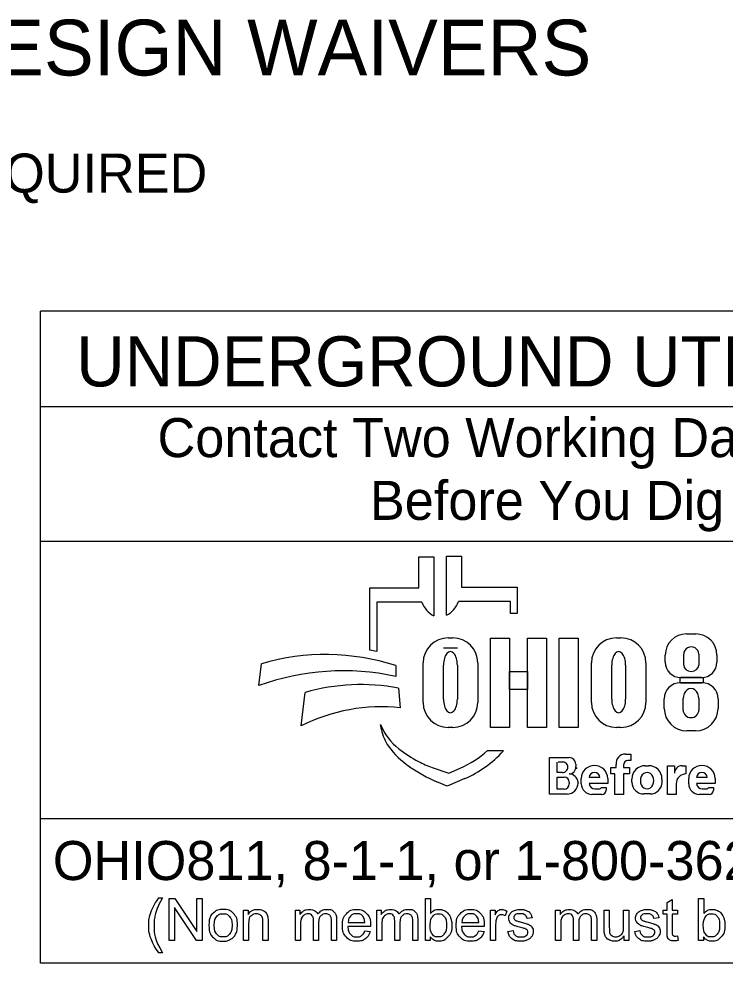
# Model space of a CAD drawing. Extents: x 39.8 to 73.8, y 13 to 35.
# Drawn here: x 42.663 to 45.194, y 15.108 to 18.494 of the extents above; entities that cross this region are included whole.
import ezdxf

# ---------------------------------------------------------------- set-up
doc = ezdxf.new("R2010")
doc.units = 0
doc.layers.add('SH_Data', color=7, linetype='Continuous')
doc.layers.add('SH_Text', color=7, linetype='Continuous')

msp = doc.modelspace()

# ---------------------------------------------------------------- linework, layer by layer
at = {"layer": 'SH_Data'}
for p, q in [((42.7405, 15.1078), (42.7405, 17.4453)), ((46.9905, 17.4453), (42.7405, 17.4453)), ((42.7405, 17.1037), (46.9905, 17.1037)), ((42.7405, 16.6203), (46.9905, 16.6203)), ((46.9905, 15.6256), (42.7405, 15.6256)), ((46.9905, 15.1078), (42.7405, 15.1078))]:
    msp.add_line(p, q, dxfattribs=at)
at = {"layer": 'SH_Text'}
for p, q in [((44.0965, 16.4533), (44.0965, 16.5648)), ((44.0965, 16.5648), (44.1502, 16.5648)), ((44.1502, 16.5648), (44.1502, 16.3527)), ((44.1958, 16.355), (44.1958, 16.5671)), ((44.1958, 16.5671), (44.2495, 16.5671)), ((44.2495, 16.5671), (44.2495, 16.4556)), ((44.2495, 16.4556), (44.4487, 16.4556)), ((44.4487, 16.4556), (44.4487, 16.3618)), ((43.9206, 16.2294), (43.9206, 16.4533)), ((43.9206, 16.4533), (44.0965, 16.4533)), ((43.9458, 16.4018), (43.9458, 16.225)), ((44.1069, 16.4018), (43.9458, 16.4018)), ((44.4254, 16.4042), (44.2391, 16.4042)), ((44.4254, 16.3618), (44.4254, 16.4042)), ((44.4487, 16.3618), (44.4254, 16.3618)), ((45.0561, 16.2881), (45.0888, 16.2881)), ((44.2015, 16.2741), (44.2181, 16.2741)), ((44.8046, 16.2741), (44.8211, 16.2741)), ((44.2348, 16.2371), (44.185, 16.2371)), ((44.112, 16.0426), (44.112, 16.1846)), ((44.3075, 16.1846), (44.3075, 16.0426)), ((44.7151, 16.0426), (44.7151, 16.1846)), ((44.9106, 16.1846), (44.9106, 16.0426)), ((44.9798, 16.1875), (44.9798, 16.2118)), ((45.0459, 16.1761), (45.0459, 16.2154)), ((45.1001, 16.2154), (45.1001, 16.1761)), ((45.1651, 16.2118), (45.1651, 16.1875)), ((43.5232, 16.1031), (43.5326, 16.1812)), ((44.0139, 16.1747), (44.0139, 16.1359)), ((44.185, 16.054), (44.185, 16.1763)), ((44.2347, 16.1763), (44.2347, 16.054)), ((44.788, 16.054), (44.788, 16.1763)), ((44.8378, 16.1763), (44.8378, 16.054)), ((45.1091, 16.1315), (45.0358, 16.1315)), ((44.0238, 16.0941), (44.0301, 16.0232)), ((45.034, 16.1132), (45.1113, 16.1132)), ((43.675, 15.9586), (43.6897, 16.0787)), ((44.9761, 16.0213), (44.9761, 16.0553)), ((45.0436, 16.0153), (45.0436, 16.0562)), ((45.1004, 16.0562), (45.1004, 16.0153)), ((45.1692, 16.0553), (45.1692, 16.0213)), ((43.9627, 15.9457), (43.9597, 15.9636)), ((44.2181, 15.9531), (44.2015, 15.9531)), ((44.8211, 15.9531), (44.8046, 15.9531)), ((45.0882, 15.9403), (45.057, 15.9403)), ((44.343, 15.8698), (44.4004, 15.8698)), ((44.8369, 15.8575), (44.8563, 15.8575)), ((44.8563, 15.8575), (44.8563, 15.8346)), ((44.5643, 15.714), (44.5643, 15.8448)), ((44.5643, 15.8448), (44.6355, 15.8448)), ((44.5923, 15.7913), (44.5923, 15.8282)), ((44.6175, 15.8282), (44.5962, 15.8282)), ((44.6592, 15.821), (44.6592, 15.8131)), ((44.8036, 15.8092), (44.8036, 15.8196)), ((44.8297, 15.8176), (44.8297, 15.8092)), ((44.8563, 15.8341), (44.8462, 15.8341)), ((44.9081, 15.8157), (44.9202, 15.8157)), ((44.9883, 15.7128), (44.9883, 15.8155)), ((44.9883, 15.8155), (45.0129, 15.8155)), ((45.0129, 15.8155), (45.0129, 15.7886)), ((45.0401, 15.8155), (45.054, 15.8155)), ((45.054, 15.8155), (45.054, 15.7859)), ((44.1446, 15.8094), (44.204, 15.7889)), ((44.204, 15.7889), (44.245, 15.8067)), ((44.6117, 15.7913), (44.5923, 15.7913)), ((44.7843, 15.7862), (44.7843, 15.8092)), ((44.7843, 15.8092), (44.8036, 15.8092)), ((44.7992, 15.7862), (44.7843, 15.7862)), ((44.7992, 15.7128), (44.7992, 15.7862)), ((44.8297, 15.8092), (44.8513, 15.8092)), ((44.8513, 15.7862), (44.8297, 15.7862)), ((44.8297, 15.7862), (44.8297, 15.7128)), ((44.8513, 15.8092), (44.8513, 15.7862)), ((44.198, 15.7419), (44.1606, 15.7583)), ((44.2613, 15.7694), (44.198, 15.7419)), ((44.5923, 15.7319), (44.5923, 15.7747)), ((44.5923, 15.7747), (44.6178, 15.7747)), ((44.6359, 15.7566), (44.6359, 15.7502)), ((44.6673, 15.7537), (44.6673, 15.7534)), ((44.6788, 15.7508), (44.6788, 15.7692)), ((44.7454, 15.7732), (44.7069, 15.7732)), ((44.7734, 15.7515), (44.707, 15.7515)), ((44.7734, 15.7692), (44.7734, 15.7515)), ((44.8603, 15.7571), (44.8603, 15.7679)), ((44.968, 15.7679), (44.968, 15.7571)), ((45.0189, 15.751), (45.0189, 15.7128)), ((45.0638, 15.7508), (45.0638, 15.7692)), ((45.1303, 15.7732), (45.0918, 15.7732)), ((45.1583, 15.7515), (45.0919, 15.7515)), ((45.1583, 15.7692), (45.1583, 15.7515)), ((44.628, 15.714), (44.5643, 15.714)), ((44.6175, 15.7319), (44.5923, 15.7319)), ((44.7522, 15.7128), (44.7168, 15.7128)), ((44.7279, 15.7323), (44.742, 15.7323)), ((44.7506, 15.7379), (44.7674, 15.7379)), ((44.7674, 15.7379), (44.7674, 15.7281)), ((44.8297, 15.7128), (44.7992, 15.7128)), ((44.9253, 15.7144), (44.9031, 15.7144)), ((45.0189, 15.7128), (44.9883, 15.7128)), ((45.1371, 15.7128), (45.1017, 15.7128)), ((45.1128, 15.7323), (45.1269, 15.7323)), ((45.1355, 15.7379), (45.1524, 15.7379)), ((45.1524, 15.7379), (45.1524, 15.7281))]:
    msp.add_line(p, q, dxfattribs=at)
for points in [[(44.3539, 16.273), (44.4219, 16.273), (44.4219, 15.9531), (44.3539, 15.9531)], [(44.4861, 16.273), (44.5541, 16.273), (44.5541, 15.9531), (44.4861, 15.9531)], [(44.5994, 16.273), (44.6682, 16.273), (44.6682, 15.9531), (44.5994, 15.9531)], [(44.4219, 16.1532), (44.4861, 16.1532), (44.4861, 16.0892), (44.4219, 16.0892)], [(45.0336, 16.1315), (45.1153, 16.1315), (45.1153, 16.113), (45.0336, 16.113)]]:
    msp.add_lwpolyline(points, close=True, dxfattribs=at)
for points in [[(43.1651, 15.3416), (43.1783, 15.3416)], [(43.2018, 15.1889), (43.2018, 15.3391), (43.2222, 15.3391), (43.3012, 15.2211), (43.3012, 15.3391), (43.3202, 15.3391), (43.3202, 15.1889), (43.2999, 15.1889), (43.2208, 15.3068), (43.2208, 15.1889), (43.2018, 15.1889)], [(44.1373, 15.1889), (44.1203, 15.1889), (44.1203, 15.3391), (44.1387, 15.3391), (44.1387, 15.2855)], [(45.1164, 15.1889), (45.0993, 15.1889), (45.0993, 15.3391), (45.1178, 15.3391), (45.1178, 15.2855)], [(44.9863, 15.2208), (44.9863, 15.2834), (44.9726, 15.2834), (44.9726, 15.2977), (44.9863, 15.2977), (44.9863, 15.3247), (45.0047, 15.3357), (45.0047, 15.2977), (45.0231, 15.2977), (45.0231, 15.2834), (45.0047, 15.2834), (45.0047, 15.2197)], [(43.4678, 15.1889), (43.4678, 15.2977), (43.4844, 15.2977), (43.4844, 15.2823)], [(43.6542, 15.1889), (43.6542, 15.2977), (43.6707, 15.2977), (43.6707, 15.2824)], [(43.9456, 15.1889), (43.9456, 15.2977), (43.9621, 15.2977), (43.9621, 15.2824)], [(44.3534, 15.1889), (44.3534, 15.2977), (44.37, 15.2977), (44.37, 15.2812)], [(44.4124, 15.2943), (44.406, 15.2772)], [(44.5866, 15.1889), (44.5866, 15.2977), (44.6031, 15.2977), (44.6031, 15.2824)], [(44.7609, 15.2303), (44.7609, 15.2977), (44.7793, 15.2977), (44.7793, 15.2374)], [(44.8306, 15.2395), (44.8306, 15.2977), (44.849, 15.2977), (44.849, 15.1889), (44.8326, 15.1889)], [(43.4862, 15.2483), (43.4862, 15.1889), (43.4678, 15.1889)], [(43.5562, 15.2558), (43.5562, 15.1889), (43.5377, 15.1889), (43.5377, 15.255)], [(43.6727, 15.2453), (43.6727, 15.1889), (43.6542, 15.1889)], [(43.7373, 15.2521), (43.7373, 15.1889), (43.7189, 15.1889), (43.7189, 15.2595)], [(43.8017, 15.2636), (43.8017, 15.1889), (43.7833, 15.1889), (43.7833, 15.2574)], [(43.923, 15.2386), (43.8418, 15.2386)], [(43.8428, 15.2537), (43.9036, 15.2537)], [(43.964, 15.2453), (43.964, 15.1889), (43.9456, 15.1889)], [(44.0287, 15.2521), (44.0287, 15.1889), (44.0103, 15.1889), (44.0103, 15.2595)], [(44.0931, 15.2636), (44.0931, 15.1889), (44.0747, 15.1889), (44.0747, 15.2574)], [(44.331, 15.2386), (44.2498, 15.2386)], [(44.2508, 15.2537), (44.3116, 15.2537)], [(44.3718, 15.2459), (44.3718, 15.1889), (44.3534, 15.1889)], [(44.5024, 15.2696), (44.4843, 15.2672)], [(44.605, 15.2453), (44.605, 15.1889), (44.5866, 15.1889)], [(44.6697, 15.2521), (44.6697, 15.1889), (44.6513, 15.1889), (44.6513, 15.2595)], [(44.7341, 15.2636), (44.7341, 15.1889), (44.7157, 15.1889), (44.7157, 15.2574)], [(44.957, 15.2696), (44.9389, 15.2672)], [(43.9034, 15.224), (43.9225, 15.2216)], [(44.1373, 15.2025), (44.1373, 15.1889)], [(44.3114, 15.224), (44.3304, 15.2216)], [(44.416, 15.2214), (44.4342, 15.2243)], [(44.8326, 15.1889), (44.8326, 15.205)], [(44.8706, 15.2214), (44.8887, 15.2243)], [(45.0231, 15.2053), (45.0257, 15.189)], [(45.1164, 15.2025), (45.1164, 15.1889)], [(43.1783, 15.1447), (43.1651, 15.1447)]]:
    msp.add_lwpolyline(points, dxfattribs=at)
for centre, radius, start, end in [((44.1983, 16.4386), 0.0985, 201.9296, 240.7469), ((44.1477, 16.4409), 0.0985, 299.2531, 338.0704), ((45.0561, 16.2118), 0.0763, 90, 180), ((45.0888, 16.2118), 0.0763, 0, 90), ((44.2015, 16.1846), 0.0895, 90, 180), ((44.2181, 16.1846), 0.0895, 0, 90), ((44.8046, 16.1846), 0.0895, 90, 180), ((44.8211, 16.1846), 0.0895, 0, 90), ((43.7924, 15.4204), 0.8191, 79.2074, 81.0007), ((43.7627, 15.3951), 0.8191, 72.1402, 106.3144), ((45.0358, 16.1875), 0.056, 180, 270), ((45.1091, 16.1875), 0.056, 270, 0), ((43.8257, 15.264), 0.8919, 77.8238, 109.8274), ((43.8896, 15.3743), 0.7322, 79.44, 105.8467), ((45.034, 16.0553), 0.0579, 90, 180), ((45.1113, 16.0553), 0.0579, 0, 90), ((43.9617, 15.3911), 0.6357, 83.8248, 116.8021), ((44.2015, 16.0426), 0.0895, 180, 270), ((44.2181, 16.0426), 0.0895, 270, 0), ((44.8046, 16.0426), 0.0895, 180, 270), ((44.8211, 16.0426), 0.0895, 270, 0), ((45.057, 16.0213), 0.081, 180, 270), ((45.0882, 16.0213), 0.081, 270, 0), ((44.147, 16.0357), 0.2008, 201.0457, 232.5314), ((44.104, 15.9698), 0.1433, 189.6817, 216.0884), ((44.2377, 16.0672), 0.3088, 216.0884, 235.7167), ((44.3396, 16.2869), 0.5173, 232.5314, 241.794), ((44.1016, 16.1372), 0.3602, 293.4582, 312.0712), ((44.1016, 16.1372), 0.401, 293.4582, 317.8286), ((44.8369, 15.824), 0.0335, 90, 187.5187), ((44.4042, 16.3114), 0.6044, 235.7167, 246.2325), ((44.2544, 16.1281), 0.3371, 241.794, 250.9821), ((44.6135, 15.8113), 0.0169, 357.8325, 90), ((44.6351, 15.8103), 0.0243, 270, 6.6529), ((44.6355, 15.821), 0.0238, 0, 90), ((44.7261, 15.7692), 0.0473, 0, 180), ((44.8462, 15.8176), 0.0165, 90, 180), ((44.9081, 15.7679), 0.0478, 90, 180), ((44.9202, 15.7679), 0.0478, 0, 90), ((45.0398, 15.7886), 0.0269, 89.2449, 180), ((45.111, 15.7692), 0.0473, 0, 180), ((44.6117, 15.81), 0.0187, 270, 2.0582), ((44.6352, 15.7539), 0.0321, 4.0748, 90), ((44.6457, 15.8088), 0.0175, 347.4023, 0), ((44.7262, 15.7722), 0.0193, 2.9632, 177.0368), ((45.0538, 15.751), 0.0349, 89.6033, 180), ((45.1111, 15.7722), 0.0193, 2.9632, 177.0368), ((44.6175, 15.7502), 0.0184, 270, 0), ((44.6178, 15.7566), 0.0181, 0, 90), ((44.628, 15.7534), 0.0393, 270, 0), ((44.6343, 15.7537), 0.033, 0, 11.7502), ((44.7168, 15.7508), 0.038, 180, 270), ((44.7279, 15.7533), 0.021, 184.827, 270), ((44.9031, 15.7571), 0.0428, 180, 270), ((44.9253, 15.7571), 0.0428, 270, 0), ((45.1017, 15.7508), 0.038, 180, 270), ((45.1128, 15.7533), 0.021, 184.827, 270), ((44.742, 15.7417), 0.00938, 270, 335.9979), ((44.7522, 15.7281), 0.0152, 270, 0), ((45.1269, 15.7417), 0.00938, 270, 335.9979), ((45.1371, 15.7281), 0.0152, 270, 0)]:
    msp.add_arc(centre, radius, start, end, dxfattribs=at)
for centre, major_axis, ratio, start_param, end_param in [((44.2099, 16.1763), (0, 0.0484), 0.514403, 4.712389, 7.853982), ((44.8129, 16.1763), (0, 0.0484), 0.514403, 4.712389, 7.853982), ((45.073, 16.2154), (0.0271, 0), 0.969373, 0, 3.141593), ((45.073, 16.1761), (0.0271, 0), 0.818453, 3.141593, 6.283185), ((45.072, 16.0562), (0, 0.0358), 0.794529, 4.712389, 7.853982), ((44.2099, 16.054), (0, 0.0484), 0.514403, 1.570796, 4.712389), ((44.8129, 16.054), (0, 0.0484), 0.514403, 1.570796, 4.712389), ((45.072, 16.0153), (0.0284, 0), 0.959837, 3.141593, 6.283185), ((44.9146, 15.7625), (0, 0.029), 0.832186, 4.712389, 7.853982), ((44.9146, 15.7625), (0, 0.0302), 0.797287, 1.570796, 4.712389)]:
    msp.add_ellipse(centre, major_axis=major_axis, ratio=ratio, start_param=start_param, end_param=end_param, dxfattribs=at)
for points in [[(43.1651, 15.1447), (43.1498, 15.164), (43.1393, 15.1898), (43.1287, 15.2156), (43.1287, 15.2432), (43.1287, 15.2676), (43.1366, 15.29), (43.1458, 15.3159), (43.1651, 15.3416)], [(43.1783, 15.3416), (43.1659, 15.3203), (43.1619, 15.3112), (43.1557, 15.297), (43.1521, 15.2817), (43.1477, 15.2625), (43.1477, 15.2431), (43.1477, 15.1939), (43.1783, 15.1447)], [(43.3443, 15.2433), (43.3443, 15.2735), (43.3611, 15.2881), (43.3751, 15.3001), (43.3953, 15.3001), (43.4177, 15.3001), (43.432, 15.2854), (43.4462, 15.2708), (43.4462, 15.2449), (43.4462, 15.2239), (43.4399, 15.2118), (43.4336, 15.1998), (43.4216, 15.1932), (43.4095, 15.1865), (43.3953, 15.1865), (43.3725, 15.1865), (43.3584, 15.2011), (43.3443, 15.2158), (43.3443, 15.2433)], [(43.3633, 15.2433), (43.3633, 15.2224), (43.3724, 15.212), (43.3815, 15.2016), (43.3953, 15.2016), (43.409, 15.2016), (43.4181, 15.2121), (43.4272, 15.2225), (43.4272, 15.2439), (43.4272, 15.2641), (43.418, 15.2745), (43.4089, 15.2849), (43.3953, 15.2849), (43.3815, 15.2849), (43.3724, 15.2746), (43.3633, 15.2642), (43.3633, 15.2433)], [(43.4844, 15.2823), (43.4964, 15.3001), (43.519, 15.3001), (43.5288, 15.3001), (43.5371, 15.2966), (43.5453, 15.2931), (43.5494, 15.2873), (43.5535, 15.2816), (43.5551, 15.2737), (43.5562, 15.2686), (43.5562, 15.2558)], [(43.5377, 15.255), (43.5377, 15.2663), (43.5356, 15.2719), (43.5334, 15.2775), (43.528, 15.2808), (43.5225, 15.2841), (43.5151, 15.2841), (43.5033, 15.2841), (43.4948, 15.2766), (43.4862, 15.2692), (43.4862, 15.2483)], [(43.6707, 15.2824), (43.6758, 15.2904), (43.6843, 15.2953), (43.6928, 15.3001), (43.7037, 15.3001), (43.7158, 15.3001), (43.7235, 15.2951), (43.7313, 15.2901), (43.7344, 15.281), (43.7474, 15.3001), (43.7681, 15.3001), (43.7843, 15.3001), (43.793, 15.2912), (43.8017, 15.2822), (43.8017, 15.2636)], [(43.7189, 15.2595), (43.7189, 15.2718), (43.7144, 15.278), (43.7099, 15.2841), (43.6996, 15.2841), (43.6918, 15.2841), (43.6852, 15.28), (43.6786, 15.2759), (43.6756, 15.268), (43.6727, 15.2602), (43.6727, 15.2453)], [(43.7833, 15.2574), (43.7833, 15.2685), (43.7815, 15.2733), (43.7797, 15.2782), (43.775, 15.2811), (43.7703, 15.2841), (43.764, 15.2841), (43.7525, 15.2841), (43.7449, 15.2765), (43.7373, 15.2689), (43.7373, 15.2521)], [(43.9225, 15.2216), (43.918, 15.2049), (43.9058, 15.1957), (43.8936, 15.1865), (43.8746, 15.1865), (43.8508, 15.1865), (43.8368, 15.2012), (43.8228, 15.2159), (43.8228, 15.2424), (43.8228, 15.2698), (43.837, 15.285), (43.8511, 15.3001), (43.8736, 15.3001), (43.8954, 15.3001), (43.9092, 15.2853), (43.9231, 15.2704), (43.9231, 15.2435), (43.9231, 15.2418), (43.923, 15.2386)], [(43.9036, 15.2537), (43.9024, 15.2675), (43.8966, 15.2743), (43.8878, 15.285), (43.8738, 15.285), (43.8611, 15.285), (43.8524, 15.2765), (43.8438, 15.268), (43.8428, 15.2537)], [(43.9621, 15.2824), (43.9672, 15.2904), (43.9757, 15.2953), (43.9842, 15.3001), (43.9951, 15.3001), (44.0072, 15.3001), (44.0149, 15.2951), (44.0226, 15.2901), (44.0258, 15.281), (44.0387, 15.3001), (44.0595, 15.3001), (44.0757, 15.3001), (44.0844, 15.2912), (44.0931, 15.2822), (44.0931, 15.2636)], [(44.0103, 15.2595), (44.0103, 15.2718), (44.0057, 15.278), (44.0012, 15.2841), (43.991, 15.2841), (43.9832, 15.2841), (43.9766, 15.28), (43.97, 15.2759), (43.967, 15.268), (43.964, 15.2602), (43.964, 15.2453)], [(44.0747, 15.2574), (44.0747, 15.2685), (44.0729, 15.2733), (44.0711, 15.2782), (44.0664, 15.2811), (44.0617, 15.2841), (44.0553, 15.2841), (44.0438, 15.2841), (44.0363, 15.2765), (44.0287, 15.2689), (44.0287, 15.2521)], [(44.1371, 15.2441), (44.1371, 15.2246), (44.1424, 15.2159), (44.1511, 15.2016), (44.1659, 15.2016), (44.178, 15.2016), (44.1868, 15.2121), (44.1956, 15.2226), (44.1956, 15.2434), (44.1956, 15.2647), (44.1871, 15.2749), (44.1787, 15.285), (44.1667, 15.285), (44.1547, 15.285), (44.1459, 15.2745), (44.1371, 15.264), (44.1371, 15.2441)], [(44.1387, 15.2855), (44.1504, 15.3001), (44.1685, 15.3001), (44.1785, 15.3001), (44.1875, 15.2961), (44.1964, 15.2921), (44.2022, 15.2847), (44.208, 15.2774), (44.2113, 15.2671), (44.2146, 15.2567), (44.2146, 15.245), (44.2146, 15.217), (44.2007, 15.2018), (44.1869, 15.1865), (44.1675, 15.1865), (44.1483, 15.1865), (44.1373, 15.2025)], [(44.3304, 15.2216), (44.3259, 15.2049), (44.3138, 15.1957), (44.3016, 15.1865), (44.2826, 15.1865), (44.2588, 15.1865), (44.2448, 15.2012), (44.2308, 15.2159), (44.2308, 15.2424), (44.2308, 15.2698), (44.2449, 15.285), (44.2591, 15.3001), (44.2816, 15.3001), (44.3034, 15.3001), (44.3172, 15.2853), (44.3311, 15.2704), (44.3311, 15.2435), (44.3311, 15.2418), (44.331, 15.2386)], [(44.3116, 15.2537), (44.3104, 15.2675), (44.3046, 15.2743), (44.2958, 15.285), (44.2818, 15.285), (44.2691, 15.285), (44.2604, 15.2765), (44.2518, 15.268), (44.2508, 15.2537)], [(44.37, 15.2812), (44.3763, 15.2928), (44.3817, 15.2965), (44.3871, 15.3001), (44.3935, 15.3001), (44.4028, 15.3001), (44.4124, 15.2943)], [(44.406, 15.2772), (44.3993, 15.2811), (44.3925, 15.2811), (44.3865, 15.2811), (44.3817, 15.2775), (44.3769, 15.2739), (44.3749, 15.2674), (44.3718, 15.2576), (44.3718, 15.2459)], [(44.4843, 15.2672), (44.4831, 15.2756), (44.4772, 15.2803), (44.4713, 15.285), (44.4605, 15.285), (44.4478, 15.285), (44.4424, 15.2808), (44.4369, 15.2766), (44.4369, 15.271), (44.4369, 15.2674), (44.4392, 15.2645), (44.4414, 15.2615), (44.4463, 15.2596), (44.449, 15.2586), (44.4626, 15.2549), (44.4822, 15.2496), (44.4899, 15.2463), (44.4977, 15.243), (44.5021, 15.2366), (44.5065, 15.2303), (44.5065, 15.2209), (44.5065, 15.2117), (44.5011, 15.2035), (44.4957, 15.1954), (44.4856, 15.191), (44.4754, 15.1865), (44.4626, 15.1865), (44.4413, 15.1865), (44.4302, 15.1953), (44.4191, 15.2041), (44.416, 15.2214)], [(44.4342, 15.2243), (44.4357, 15.2133), (44.4428, 15.2074), (44.4498, 15.2016), (44.4624, 15.2016), (44.4752, 15.2016), (44.4813, 15.2068), (44.4875, 15.212), (44.4875, 15.2189), (44.4875, 15.2252), (44.4821, 15.2288), (44.4783, 15.2313), (44.4632, 15.235), (44.4429, 15.2402), (44.435, 15.2439), (44.4272, 15.2476), (44.4231, 15.2542), (44.4191, 15.2608), (44.4191, 15.2688), (44.4191, 15.2761), (44.4224, 15.2823), (44.4257, 15.2885), (44.4315, 15.2926), (44.4358, 15.2957), (44.4432, 15.2979), (44.4507, 15.3001), (44.4592, 15.3001), (44.472, 15.3001), (44.4817, 15.2964), (44.4914, 15.2928), (44.496, 15.2865), (44.5006, 15.2801), (44.5024, 15.2696)], [(44.6031, 15.2824), (44.6082, 15.2904), (44.6167, 15.2953), (44.6252, 15.3001), (44.6361, 15.3001), (44.6482, 15.3001), (44.6559, 15.2951), (44.6636, 15.2901), (44.6668, 15.281), (44.6797, 15.3001), (44.7005, 15.3001), (44.7167, 15.3001), (44.7254, 15.2912), (44.7341, 15.2822), (44.7341, 15.2636)], [(44.6513, 15.2595), (44.6513, 15.2718), (44.6467, 15.278), (44.6422, 15.2841), (44.632, 15.2841), (44.6242, 15.2841), (44.6176, 15.28), (44.611, 15.2759), (44.608, 15.268), (44.605, 15.2602), (44.605, 15.2453)], [(44.7157, 15.2574), (44.7157, 15.2685), (44.7139, 15.2733), (44.7121, 15.2782), (44.7074, 15.2811), (44.7027, 15.2841), (44.6963, 15.2841), (44.6848, 15.2841), (44.6773, 15.2765), (44.6697, 15.2689), (44.6697, 15.2521)], [(44.9389, 15.2672), (44.9376, 15.2756), (44.9317, 15.2803), (44.9258, 15.285), (44.9151, 15.285), (44.9024, 15.285), (44.8969, 15.2808), (44.8915, 15.2766), (44.8915, 15.271), (44.8915, 15.2674), (44.8938, 15.2645), (44.896, 15.2615), (44.9008, 15.2596), (44.9036, 15.2586), (44.9171, 15.2549), (44.9367, 15.2496), (44.9445, 15.2463), (44.9522, 15.243), (44.9567, 15.2366), (44.9611, 15.2303), (44.9611, 15.2209), (44.9611, 15.2117), (44.9557, 15.2035), (44.9503, 15.1954), (44.9401, 15.191), (44.93, 15.1865), (44.9171, 15.1865), (44.8959, 15.1865), (44.8848, 15.1953), (44.8736, 15.2041), (44.8706, 15.2214)], [(44.8887, 15.2243), (44.8903, 15.2133), (44.8973, 15.2074), (44.9044, 15.2016), (44.917, 15.2016), (44.9297, 15.2016), (44.9359, 15.2068), (44.9421, 15.212), (44.9421, 15.2189), (44.9421, 15.2252), (44.9366, 15.2288), (44.9328, 15.2313), (44.9177, 15.235), (44.8974, 15.2402), (44.8896, 15.2439), (44.8817, 15.2476), (44.8777, 15.2542), (44.8736, 15.2608), (44.8736, 15.2688), (44.8736, 15.2761), (44.877, 15.2823), (44.8803, 15.2885), (44.8861, 15.2926), (44.8904, 15.2957), (44.8978, 15.2979), (44.9052, 15.3001), (44.9138, 15.3001), (44.9266, 15.3001), (44.9363, 15.2964), (44.946, 15.2928), (44.9506, 15.2865), (44.9552, 15.2801), (44.957, 15.2696)], [(45.1161, 15.2441), (45.1161, 15.2246), (45.1215, 15.2159), (45.1302, 15.2016), (45.145, 15.2016), (45.157, 15.2016), (45.1658, 15.2121), (45.1746, 15.2226), (45.1746, 15.2434), (45.1746, 15.2647), (45.1662, 15.2749), (45.1578, 15.285), (45.1458, 15.285), (45.1337, 15.285), (45.1249, 15.2745), (45.1161, 15.264), (45.1161, 15.2441)], [(45.1178, 15.2855), (45.1294, 15.3001), (45.1475, 15.3001), (45.1576, 15.3001), (45.1665, 15.2961), (45.1755, 15.2921), (45.1813, 15.2847), (45.1871, 15.2774), (45.1903, 15.2671), (45.1936, 15.2567), (45.1936, 15.245), (45.1936, 15.217), (45.1798, 15.2018), (45.166, 15.1865), (45.1466, 15.1865), (45.1273, 15.1865), (45.1164, 15.2025)], [(43.8418, 15.2386), (43.8428, 15.2207), (43.852, 15.2111), (43.8611, 15.2016), (43.8747, 15.2016), (43.8849, 15.2016), (43.892, 15.207), (43.8992, 15.2123), (43.9034, 15.224)], [(44.2498, 15.2386), (44.2508, 15.2207), (44.26, 15.2111), (44.2691, 15.2016), (44.2827, 15.2016), (44.2929, 15.2016), (44.3, 15.207), (44.3072, 15.2123), (44.3114, 15.224)], [(44.7793, 15.2374), (44.7793, 15.223), (44.7805, 15.218), (44.7822, 15.2107), (44.7878, 15.2066), (44.7935, 15.2024), (44.8018, 15.2024), (44.81, 15.2024), (44.8173, 15.2067), (44.8246, 15.2109), (44.8276, 15.2182), (44.8306, 15.2255), (44.8306, 15.2395)], [(44.8326, 15.205), (44.8199, 15.1865), (44.7981, 15.1865), (44.7884, 15.1865), (44.7801, 15.1902), (44.7718, 15.1939), (44.7677, 15.1995), (44.7637, 15.205), (44.762, 15.2131), (44.7609, 15.2186), (44.7609, 15.2303)], [(45.0257, 15.189), (45.018, 15.1874), (45.0118, 15.1874), (45.0018, 15.1874), (44.9963, 15.1906), (44.9908, 15.1938), (44.9885, 15.199), (44.9863, 15.2041), (44.9863, 15.2208)], [(45.0047, 15.2197), (45.0047, 15.2118), (45.0056, 15.2095), (45.0066, 15.2073), (45.0088, 15.2059), (45.011, 15.2046), (45.0151, 15.2046), (45.0181, 15.2046), (45.0231, 15.2053)]]:
    msp.add_open_spline(points, degree=3, dxfattribs=at)

# ---------------------------------------------------------------- texts
for s, height, p in [('ADA DESIGN WAIVERS', 0.2, (41.7574, 18.2906)), ('NONE REQUIRED', 0.14, (41.7574, 17.8706)), ('UNDERGROUND UTILITIES', 0.18, (42.8686, 17.1756)), ('Contact Two Working Days', 0.14, (43.1601, 16.9221)), ('Before You Dig', 0.14, (43.9213, 16.6971)), ('OHIO811, 8-1-1, or 1-800-362-2764', 0.14, (42.785, 15.4056))]:
    msp.add_text(s, height=height, dxfattribs=at).set_placement(p)

doc.saveas('drawing.dxf')
